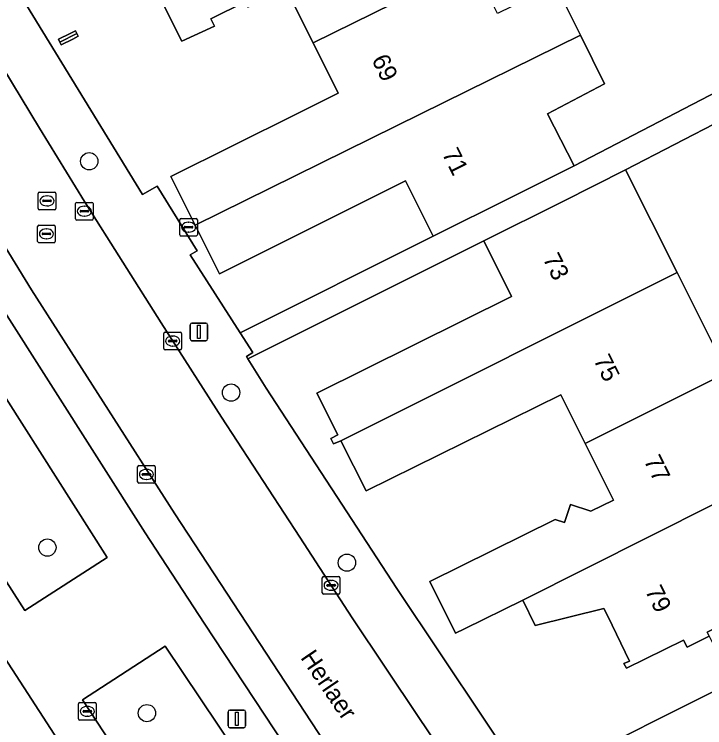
# Model space of a CAD drawing. Extents: x 157793 to 159380, y 380877 to 382313.
# Drawn here: x 158180.74 to 158219.83, y 381465.24 to 381505.64 of the extents above; entities that cross this region are included whole.
import ezdxf

# ---------------------------------------------------------------- set-up
doc = ezdxf.new("R2010")
doc.units = 0
for name, color, linetype in [('IMGEO_Boom', 7, 'Continuous'), ('IMGEO_Erf', 7, 'Continuous'), ('IMGEO_Groenvoorziening', 7, 'Continuous'), ('IMGEO_Kolk', 7, 'Continuous'), ('IMGEO_Lichtmast', 7, 'Continuous'), ('IMGEO_Openbare_ruimte_label', 7, 'Continuous'), ('IMGEO_Pand', 7, 'Continuous'), ('IMGEO_Pand_nummerreeks', 7, 'Continuous'), ('IMGEO_Parkeervlak_open', 7, 'Continuous'), ('IMGEO_Rijbaan_lokaal_open', 7, 'Continuous'), ('IMGEO_Rioolput', 7, 'Continuous'), ('IMGEO_Voetpad_open', 7, 'Continuous')]:
    doc.layers.add(name, color=color, linetype=linetype)

msp = doc.modelspace()

# ---------------------------------------------------------------- linework, layer by layer
at = {"layer": 'IMGEO_Boom'}
for centre in [(158184.986, 381497.315), (158193.018, 381484.217), (158182.617, 381475.445), (158199.576, 381474.588), (158188.251, 381466.07)]:
    msp.add_circle(centre, 0.489, dxfattribs=at)
at = {"layer": 'IMGEO_Erf'}
for points in [[(158181.083, 381506.764), (158188.007, 381495.43), (158188.833, 381495.915), (158191.096, 381492.237), (158190.7, 381492.013), (158193.532, 381487.602), (158204.46, 381493.068), (158202.889, 381496.209), (158192.361, 381490.942), (158190.983, 381493.696), (158189.601, 381496.459), (158196.733, 381500), (158199.076, 381501.163), (158197.657, 381504.028), (158196.125, 381507.123)], [(158211.379, 381507.303), (158212.789, 381504.457), (158214.158, 381501.692), (158210.927, 381500), (158212.434, 381497.057), (158222.963, 381502.539)], [(158193.811, 381506.345), (158191.865, 381505.385), (158192.073, 381504.963), (158190.226, 381504.118), (158188.912, 381506.75)], [(158223.667, 381501.139), (158215.352, 381496.827), (158218.262, 381491.01), (158221.092, 381485.355)], [(158196.197, 381444.89), (158187.383, 381458.121), (158179.308, 381470.565), (158168.261, 381487.773), (158162.146, 381497.834)], [(158207.322, 381492.809), (158193.967, 381486.126), (158195.005, 381484.47), (158202.402, 381473.13), (158209.819, 381462.024), (158210.491, 381462.328), (158213.909, 381457.425), (158213.23, 381457.086), (158215.155, 381454.363), (158215.033, 381454.286), (158220.925, 381445.928)], [(158220.077, 381470.42), (158218.834, 381469.798), (158218.628, 381470.209), (158215.399, 381468.609), (158215.254, 381468.886), (158215.575, 381469.021), (158214.338, 381471.558), (158214.128, 381471.988), (158210.227, 381471.034), (158209.526, 381472.475), (158206.23, 381470.85), (158205.719, 381470.594), (158204.278, 381473.518), (158211.36, 381477.029), (158211.892, 381476.869), (158212.238, 381477.889), (158213.378, 381477.503), (158214.666, 381478.129), (158213.061, 381481.336), (158211.687, 381484.083), (158200.657, 381478.649), (158199.236, 381481.489), (158198.823, 381481.322), (158198.673, 381481.621), (158199.069, 381481.82), (158197.881, 381484.193), (158208.896, 381489.662), (158207.322, 381492.809)], [(158224.056, 381462.381), (158214.071, 381457.386), (158212.773, 381459.981), (158211.362, 381462.801), (158221.381, 381467.814)]]:
    msp.add_lwpolyline(points, dxfattribs=at)
msp.add_lwpolyline([(158184.213, 381504.7), (158184.291, 381504.541), (158184.365, 381504.392), (158184.052, 381504.237), (158183.399, 381503.914), (158183.324, 381504.066), (158183.247, 381504.221), (158183.899, 381504.544)], close=True, dxfattribs=at)
at = {"layer": 'IMGEO_Groenvoorziening'}
for points in [[(158177.476, 381488.273), (158172.552, 381485.604), (158181.337, 381471.872), (158186.001, 381474.885)], [(158189.292, 381469.869), (158184.614, 381466.823), (158191.129, 381456.883), (158198.958, 381445.276), (158200.372, 381442.689), (158206.681, 381444.18), (158201.324, 381451.912)]]:
    msp.add_lwpolyline(points, close=True, dxfattribs=at)
at = {"layer": 'IMGEO_Kolk'}
for p, q in [((158190.108, 381493.156), (158190.108, 381494.008)), ((158190.183, 381494.082), (158191.035, 381494.082)), ((158191.109, 381494.008), (158191.109, 381493.156)), ((158190.367, 381493.576), (158190.367, 381493.588)), ((158190.41, 381493.625), (158190.808, 381493.625)), ((158190.596, 381493.862), (158190.621, 381493.862)), ((158190.851, 381493.588), (158190.851, 381493.576)), ((158190.805, 381493.539), (158190.407, 381493.539)), ((158190.619, 381493.302), (158190.594, 381493.302)), ((158191.035, 381493.082), (158190.183, 381493.082)), ((158189.211, 381486.71), (158189.211, 381487.562)), ((158189.286, 381487.636), (158190.138, 381487.636)), ((158190.212, 381487.562), (158190.212, 381486.71)), ((158189.47, 381487.13), (158189.47, 381487.142)), ((158189.513, 381487.179), (158189.911, 381487.179)), ((158189.699, 381487.416), (158189.724, 381487.416)), ((158189.954, 381487.142), (158189.954, 381487.13)), ((158189.908, 381487.093), (158189.51, 381487.093)), ((158189.722, 381486.856), (158189.697, 381486.856)), ((158190.138, 381486.636), (158189.286, 381486.636)), ((158187.725, 381479.16), (158187.725, 381480.012)), ((158187.8, 381480.086), (158188.652, 381480.086)), ((158188.213, 381479.866), (158188.238, 381479.866)), ((158188.726, 381480.012), (158188.726, 381479.16)), ((158187.984, 381479.58), (158187.984, 381479.592)), ((158188.422, 381479.543), (158188.024, 381479.543)), ((158188.027, 381479.629), (158188.425, 381479.629)), ((158188.468, 381479.592), (158188.468, 381479.58)), ((158188.652, 381479.086), (158187.8, 381479.086)), ((158188.236, 381479.306), (158188.211, 381479.306)), ((158198.256, 381473.808), (158199.108, 381473.808)), ((158198.181, 381472.882), (158198.181, 381473.734)), ((158198.669, 381473.588), (158198.694, 381473.588)), ((158199.182, 381473.734), (158199.182, 381472.882)), ((158198.44, 381473.302), (158198.44, 381473.314)), ((158198.878, 381473.265), (158198.48, 381473.265)), ((158198.483, 381473.351), (158198.881, 381473.351)), ((158198.692, 381473.028), (158198.667, 381473.028)), ((158198.924, 381473.314), (158198.924, 381473.302)), ((158199.108, 381472.808), (158198.256, 381472.808)), ((158184.377, 381465.747), (158184.377, 381466.599)), ((158184.452, 381466.673), (158185.304, 381466.673)), ((158185.378, 381466.599), (158185.378, 381465.747)), ((158184.636, 381466.167), (158184.636, 381466.179)), ((158185.074, 381466.13), (158184.676, 381466.13)), ((158184.679, 381466.216), (158185.077, 381466.216)), ((158184.865, 381466.453), (158184.89, 381466.453)), ((158185.12, 381466.179), (158185.12, 381466.167)), ((158184.888, 381465.893), (158184.863, 381465.893)), ((158185.304, 381465.673), (158184.452, 381465.673))]:
    msp.add_line(p, q, dxfattribs=at)
for points in [[(158190.108, 381493.156), (158190.108, 381494.008)], [(158190.183, 381494.082), (158191.035, 381494.082)], [(158191.109, 381494.008), (158191.109, 381493.156)], [(158191.035, 381493.082), (158190.183, 381493.082)], [(158189.211, 381486.71), (158189.211, 381487.562)], [(158189.286, 381487.636), (158190.138, 381487.636)], [(158190.212, 381487.562), (158190.212, 381486.71)], [(158190.138, 381486.636), (158189.286, 381486.636)], [(158187.725, 381479.16), (158187.725, 381480.012)], [(158187.8, 381480.086), (158188.652, 381480.086)], [(158188.726, 381480.012), (158188.726, 381479.16)], [(158188.652, 381479.086), (158187.8, 381479.086)], [(158198.256, 381473.808), (158199.108, 381473.808)], [(158198.181, 381472.882), (158198.181, 381473.734)], [(158199.182, 381473.734), (158199.182, 381472.882)], [(158199.108, 381472.808), (158198.256, 381472.808)], [(158184.377, 381465.747), (158184.377, 381466.599)], [(158184.452, 381466.673), (158185.304, 381466.673)], [(158185.378, 381466.599), (158185.378, 381465.747)], [(158185.304, 381465.673), (158184.452, 381465.673)]]:
    msp.add_lwpolyline(points, dxfattribs=at)
for centre, radius, start, end in [((158190.185, 381494.006), 0.0765, 91.552, 178.448), ((158190.185, 381494.006), 0.0765, 91.552, 178.448), ((158191.033, 381494.006), 0.0765, 1.552, 88.448), ((158191.033, 381494.006), 0.0765, 1.552, 88.448), ((158190.407, 381493.585), 0.0403, 85.8775, 175.7526), ((158190.404, 381493.575), 0.0366, 178.938, 274.7102), ((158190.808, 381493.582), 0.043, 264.8664, 352.4533), ((158190.812, 381493.587), 0.0386, 1.7309, 96.639), ((158190.185, 381493.158), 0.0765, 181.552, 268.448), ((158190.185, 381493.158), 0.0765, 181.552, 268.448), ((158191.033, 381493.158), 0.0765, 271.552, 358.448), ((158191.033, 381493.158), 0.0765, 271.552, 358.448), ((158189.288, 381487.56), 0.0765, 91.552, 178.448), ((158189.288, 381487.56), 0.0765, 91.552, 178.448), ((158190.136, 381487.56), 0.0765, 1.552, 88.448), ((158190.136, 381487.56), 0.0765, 1.552, 88.448), ((158189.51, 381487.139), 0.0403, 85.8775, 175.7526), ((158189.507, 381487.129), 0.0366, 178.938, 274.7102), ((158189.911, 381487.136), 0.043, 264.8664, 352.4533), ((158189.915, 381487.141), 0.0386, 1.7309, 96.639), ((158189.288, 381486.712), 0.0765, 181.552, 268.448), ((158189.288, 381486.712), 0.0765, 181.552, 268.448), ((158190.136, 381486.712), 0.0765, 271.552, 358.448), ((158190.136, 381486.712), 0.0765, 271.552, 358.448), ((158187.802, 381480.01), 0.0765, 91.552, 178.448), ((158187.802, 381480.01), 0.0765, 91.552, 178.448), ((158188.65, 381480.01), 0.0765, 1.552, 88.448), ((158188.65, 381480.01), 0.0765, 1.552, 88.448), ((158188.024, 381479.589), 0.0403, 85.8775, 175.7526), ((158188.021, 381479.579), 0.0366, 178.938, 274.7102), ((158188.425, 381479.586), 0.043, 264.8664, 352.4533), ((158188.429, 381479.591), 0.0386, 1.7309, 96.639), ((158187.802, 381479.162), 0.0765, 181.552, 268.448), ((158187.802, 381479.162), 0.0765, 181.552, 268.448), ((158188.65, 381479.162), 0.0765, 271.552, 358.448), ((158188.65, 381479.162), 0.0765, 271.552, 358.448), ((158198.258, 381473.732), 0.0765, 91.552, 178.448), ((158198.258, 381473.732), 0.0765, 91.552, 178.448), ((158199.106, 381473.732), 0.0765, 1.552, 88.448), ((158199.106, 381473.732), 0.0765, 1.552, 88.448), ((158198.48, 381473.311), 0.0403, 85.8775, 175.7526), ((158198.477, 381473.301), 0.0366, 178.938, 274.7102), ((158198.881, 381473.308), 0.043, 264.8664, 352.4533), ((158198.885, 381473.313), 0.0386, 1.7309, 96.639), ((158198.258, 381472.884), 0.0765, 181.552, 268.448), ((158198.258, 381472.884), 0.0765, 181.552, 268.448), ((158199.106, 381472.884), 0.0765, 271.552, 358.448), ((158199.106, 381472.884), 0.0765, 271.552, 358.448), ((158184.454, 381466.597), 0.0765, 91.552, 178.448), ((158184.454, 381466.597), 0.0765, 91.552, 178.448), ((158185.302, 381466.597), 0.0765, 1.552, 88.448), ((158185.302, 381466.597), 0.0765, 1.552, 88.448), ((158184.676, 381466.176), 0.0403, 85.8775, 175.7526), ((158184.673, 381466.166), 0.0366, 178.938, 274.7102), ((158185.077, 381466.173), 0.043, 264.8664, 352.4533), ((158185.081, 381466.178), 0.0386, 1.7309, 96.639), ((158184.454, 381465.749), 0.0765, 181.552, 268.448), ((158184.454, 381465.749), 0.0765, 181.552, 268.448), ((158185.302, 381465.749), 0.0765, 271.552, 358.448), ((158185.302, 381465.749), 0.0765, 271.552, 358.448)]:
    msp.add_arc(centre, radius, start, end, dxfattribs=at)
for centre, major_axis, ratio, start_param, end_param in [((158190.595, 381493.582), (-0.387, 0.002), 0.722429, 4.712389, 7.853982), ((158190.62, 381493.582), (-0.39, 0.002), 0.717154, 1.570796, 4.712389), ((158189.698, 381487.136), (-0.387, 0.002), 0.722429, 4.712389, 7.853982), ((158189.723, 381487.136), (-0.39, 0.002), 0.717154, 1.570796, 4.712389), ((158188.212, 381479.586), (-0.387, 0.002), 0.722429, 4.712389, 7.853982), ((158188.237, 381479.586), (-0.39, 0.002), 0.717154, 1.570796, 4.712389), ((158198.668, 381473.308), (-0.387, 0.002), 0.722429, 4.712389, 7.853982), ((158198.693, 381473.308), (-0.39, 0.002), 0.717154, 1.570796, 4.712389), ((158184.864, 381466.173), (-0.387, 0.002), 0.722429, 4.712389, 7.853982), ((158184.889, 381466.173), (-0.39, 0.002), 0.717154, 1.570796, 4.712389)]:
    msp.add_ellipse(centre, major_axis=major_axis, ratio=ratio, start_param=start_param, end_param=end_param, dxfattribs=at)
at = {"layer": 'IMGEO_Lichtmast'}
for p, q in [((158190.701, 381487.254), (158190.701, 381488.054)), ((158190.701, 381488.054), (158190.701, 381487.254)), ((158190.801, 381488.154), (158191.591, 381488.154)), ((158191.591, 381488.154), (158190.801, 381488.154)), ((158191.691, 381488.054), (158191.691, 381487.254)), ((158191.691, 381487.254), (158191.691, 381488.054)), ((158191.591, 381487.154), (158190.801, 381487.154)), ((158190.801, 381487.154), (158191.591, 381487.154)), ((158192.851, 381465.343), (158192.851, 381466.143)), ((158192.851, 381466.143), (158192.851, 381465.343)), ((158192.951, 381466.243), (158193.741, 381466.243)), ((158193.741, 381466.243), (158192.951, 381466.243)), ((158193.841, 381466.143), (158193.841, 381465.343)), ((158193.841, 381465.343), (158193.841, 381466.143)), ((158193.741, 381465.243), (158192.951, 381465.243)), ((158192.951, 381465.243), (158193.741, 381465.243))]:
    msp.add_line(p, q, dxfattribs=at)
for points in [[(158191.121, 381488.029), (158191.271, 381488.029), (158191.271, 381487.279), (158191.121, 381487.279), (158191.121, 381488.029)], [(158193.271, 381466.118), (158193.421, 381466.118), (158193.421, 381465.368), (158193.271, 381465.368), (158193.271, 381466.118)]]:
    msp.add_lwpolyline(points, dxfattribs=at)
for centre, start, end in [((158190.801, 381488.054), 90, 180), ((158190.801, 381488.054), 90, 180), ((158191.591, 381488.054), 0, 90), ((158191.591, 381488.054), 360, 90), ((158190.801, 381487.254), 180, 270), ((158190.801, 381487.254), 180, 270), ((158191.591, 381487.254), 270, 0), ((158191.591, 381487.254), 270, 0), ((158192.951, 381466.143), 90, 180), ((158192.951, 381466.143), 90, 180), ((158193.741, 381466.143), 0, 90), ((158193.741, 381466.143), 360, 90), ((158192.951, 381465.343), 180, 270), ((158192.951, 381465.343), 180, 270), ((158193.741, 381465.343), 270, 0), ((158193.741, 381465.343), 270, 0)]:
    msp.add_arc(centre, 0.1, start, end, dxfattribs=at)
at = {"layer": 'IMGEO_Pand'}
for points in [[(158205.616, 381507.956), (158205.476, 381508.238), (158205.222, 381508.751), (158204.106, 381511.004), (158206.692, 381512.285), (158205.402, 381514.888), (158188.912, 381506.75), (158190.226, 381504.118), (158192.073, 381504.963), (158191.865, 381505.385), (158193.811, 381506.345), (158193.957, 381506.049), (158196.125, 381507.123), (158197.657, 381504.028)], [(158212.789, 381504.457), (158211.379, 381507.303), (158208.099, 381505.678), (158206.609, 381508.687), (158205.578, 381508.178), (158205.673, 381507.984), (158205.616, 381507.956), (158197.657, 381504.028), (158199.076, 381501.163), (158196.733, 381500), (158189.601, 381496.459), (158190.983, 381493.696), (158203.757, 381500)], [(158183.324, 381504.066), (158184.291, 381504.541), (158184.213, 381504.7), (158183.899, 381504.544), (158183.247, 381504.221)], [(158184.052, 381504.237), (158184.365, 381504.392), (158184.291, 381504.541), (158183.324, 381504.066), (158183.399, 381503.914)], [(158212.789, 381504.457), (158203.757, 381500), (158190.983, 381493.696), (158192.361, 381490.942), (158202.889, 381496.209), (158204.46, 381493.068), (158208.932, 381495.305), (158212.434, 381497.057), (158210.927, 381500), (158214.158, 381501.692)], [(158199.236, 381481.489), (158218.262, 381491.01), (158215.352, 381496.827), (158211.794, 381495.047), (158207.322, 381492.809), (158208.896, 381489.662), (158197.881, 381484.193), (158199.069, 381481.82), (158198.673, 381481.621), (158198.823, 381481.322)], [(158221.092, 381485.355), (158218.262, 381491.01), (158199.236, 381481.489), (158200.657, 381478.649), (158211.687, 381484.083), (158213.061, 381481.336)], [(158221.092, 381485.355), (158213.061, 381481.336), (158214.666, 381478.129), (158213.378, 381477.503), (158212.238, 381477.889), (158211.892, 381476.869), (158211.36, 381477.029), (158204.278, 381473.518), (158205.719, 381470.594), (158206.23, 381470.85), (158209.526, 381472.475), (158223.921, 381479.701)], [(158209.526, 381472.475), (158210.227, 381471.034), (158214.128, 381471.988), (158214.338, 381471.558), (158215.575, 381469.021), (158215.254, 381468.886), (158215.399, 381468.609), (158218.628, 381470.209), (158218.834, 381469.798), (158220.077, 381470.42), (158219.962, 381470.65), (158226.59, 381473.967), (158226.441, 381474.264), (158226.601, 381474.344), (158225.241, 381477.063), (158225.983, 381477.435), (158227.662, 381478.929), (158226.602, 381481.047), (158223.921, 381479.701)], [(158212.773, 381459.981), (158230.582, 381468.893), (158227.604, 381474.845), (158226.869, 381474.478), (158226.601, 381474.344), (158226.441, 381474.264), (158226.59, 381473.967), (158219.962, 381470.65), (158220.077, 381470.42), (158221.381, 381467.814), (158211.362, 381462.801)]]:
    msp.add_lwpolyline(points, close=True, dxfattribs=at)
at = {"layer": 'IMGEO_Parkeervlak_open'}
for points in [[(158211.021, 381445.909), (158206.462, 381452.438), (158198.314, 381464.433), (158189.837, 381477.355), (158181.714, 381490.043), (158173.283, 381503.774), (158168.753, 381511.382), (158162.831, 381521.68), (158157.089, 381532.018), (158155.415, 381535.054), (158148.825, 381547.056)], [(158148.449, 381543.56), (158152.339, 381536.528), (158154.693, 381532.233), (158161.1, 381520.669), (158163.584, 381516.344), (158167.051, 381510.356), (158171.612, 381502.714), (158176.956, 381493.981), (158180.068, 381488.973), (158188.156, 381476.274), (158191.493, 381471.166), (158196.6, 381463.411), (158207.708, 381447.175)]]:
    msp.add_lwpolyline(points, dxfattribs=at)
at = {"layer": 'IMGEO_Rijbaan_lokaal_open'}
msp.add_lwpolyline([(158168.753, 381511.382), (158173.283, 381503.774), (158181.714, 381490.043), (158189.837, 381477.355), (158198.314, 381464.433), (158206.462, 381452.438), (158211.021, 381445.909), (158211.178, 381445.694), (158214.031, 381441.646), (158215.433, 381439.703), (158215.544, 381439.782), (158219.673, 381442.728), (158211.139, 381454.855), (158207.189, 381460.583), (158203.651, 381465.824), (158199.88, 381471.47), (158196.908, 381476.029), (158192.482, 381482.833), (158189.052, 381488.161), (158184.727, 381495.042), (158182.168, 381499.189), (158178.499, 381505.249), (158175.691, 381509.903)], dxfattribs=at)
at = {"layer": 'IMGEO_Rioolput'}
for p, q in [((158182.096, 381494.646), (158182.096, 381495.498)), ((158182.171, 381495.572), (158183.023, 381495.572)), ((158182.584, 381495.352), (158182.609, 381495.352)), ((158183.097, 381495.498), (158183.097, 381494.646)), ((158182.355, 381495.066), (158182.355, 381495.078)), ((158182.793, 381495.029), (158182.395, 381495.029)), ((158182.398, 381495.115), (158182.796, 381495.115)), ((158182.607, 381494.792), (158182.582, 381494.792)), ((158182.839, 381495.078), (158182.839, 381495.066)), ((158184.211, 381494.064), (158184.211, 381494.916)), ((158184.286, 381494.99), (158185.138, 381494.99)), ((158185.212, 381494.916), (158185.212, 381494.064)), ((158183.023, 381494.572), (158182.171, 381494.572)), ((158184.47, 381494.484), (158184.47, 381494.496)), ((158184.908, 381494.447), (158184.51, 381494.447)), ((158184.513, 381494.533), (158184.911, 381494.533)), ((158184.699, 381494.77), (158184.724, 381494.77)), ((158184.954, 381494.496), (158184.954, 381494.484)), ((158185.138, 381493.99), (158184.286, 381493.99)), ((158184.722, 381494.21), (158184.697, 381494.21)), ((158182.064, 381492.78), (158182.064, 381493.632)), ((158182.139, 381493.706), (158182.991, 381493.706)), ((158183.065, 381493.632), (158183.065, 381492.78)), ((158182.323, 381493.2), (158182.323, 381493.212)), ((158182.366, 381493.249), (158182.764, 381493.249)), ((158182.552, 381493.486), (158182.577, 381493.486)), ((158182.807, 381493.212), (158182.807, 381493.2)), ((158182.761, 381493.163), (158182.363, 381493.163)), ((158182.575, 381492.926), (158182.55, 381492.926)), ((158182.991, 381492.706), (158182.139, 381492.706))]:
    msp.add_line(p, q, dxfattribs=at)
for points in [[(158182.096, 381494.646), (158182.096, 381495.498)], [(158182.171, 381495.572), (158183.023, 381495.572)], [(158183.097, 381495.498), (158183.097, 381494.646)], [(158184.211, 381494.064), (158184.211, 381494.916)], [(158184.286, 381494.99), (158185.138, 381494.99)], [(158185.212, 381494.916), (158185.212, 381494.064)], [(158183.023, 381494.572), (158182.171, 381494.572)], [(158185.138, 381493.99), (158184.286, 381493.99)], [(158182.064, 381492.78), (158182.064, 381493.632)], [(158182.139, 381493.706), (158182.991, 381493.706)], [(158183.065, 381493.632), (158183.065, 381492.78)], [(158182.991, 381492.706), (158182.139, 381492.706)]]:
    msp.add_lwpolyline(points, dxfattribs=at)
for centre, radius, start, end in [((158182.173, 381495.496), 0.0765, 91.552, 178.448), ((158182.173, 381495.496), 0.0765, 91.552, 178.448), ((158183.021, 381495.496), 0.0765, 1.552, 88.448), ((158183.021, 381495.496), 0.0765, 1.552, 88.448), ((158182.395, 381495.075), 0.0403, 85.8775, 175.7526), ((158182.392, 381495.065), 0.0366, 178.938, 274.7102), ((158182.796, 381495.072), 0.043, 264.8664, 352.4533), ((158182.8, 381495.077), 0.0386, 1.7309, 96.639), ((158184.288, 381494.914), 0.0765, 91.552, 178.448), ((158184.288, 381494.914), 0.0765, 91.552, 178.448), ((158185.136, 381494.914), 0.0765, 1.552, 88.448), ((158185.136, 381494.914), 0.0765, 1.552, 88.448), ((158182.173, 381494.648), 0.0765, 181.552, 268.448), ((158182.173, 381494.648), 0.0765, 181.552, 268.448), ((158183.021, 381494.648), 0.0765, 271.552, 358.448), ((158183.021, 381494.648), 0.0765, 271.552, 358.448), ((158184.51, 381494.493), 0.0403, 85.8775, 175.7526), ((158184.507, 381494.483), 0.0366, 178.938, 274.7102), ((158184.911, 381494.49), 0.043, 264.8664, 352.4533), ((158184.915, 381494.495), 0.0386, 1.7309, 96.639), ((158184.288, 381494.066), 0.0765, 181.552, 268.448), ((158184.288, 381494.066), 0.0765, 181.552, 268.448), ((158185.136, 381494.066), 0.0765, 271.552, 358.448), ((158185.136, 381494.066), 0.0765, 271.552, 358.448), ((158182.141, 381493.63), 0.0765, 91.552, 178.448), ((158182.141, 381493.63), 0.0765, 91.552, 178.448), ((158182.989, 381493.63), 0.0765, 1.552, 88.448), ((158182.989, 381493.63), 0.0765, 1.552, 88.448), ((158182.363, 381493.209), 0.0403, 85.8775, 175.7526), ((158182.36, 381493.199), 0.0366, 178.938, 274.7102), ((158182.764, 381493.206), 0.043, 264.8664, 352.4533), ((158182.768, 381493.211), 0.0386, 1.7309, 96.639), ((158182.141, 381492.782), 0.0765, 181.552, 268.448), ((158182.141, 381492.782), 0.0765, 181.552, 268.448), ((158182.989, 381492.782), 0.0765, 271.552, 358.448), ((158182.989, 381492.782), 0.0765, 271.552, 358.448)]:
    msp.add_arc(centre, radius, start, end, dxfattribs=at)
for centre, major_axis, ratio, start_param, end_param in [((158182.583, 381495.072), (-0.387, 0.002), 0.722429, 4.712389, 7.853982), ((158182.608, 381495.072), (-0.39, 0.002), 0.717154, 1.570796, 4.712389), ((158184.698, 381494.49), (-0.387, 0.002), 0.722429, 4.712389, 7.853982), ((158184.723, 381494.49), (-0.39, 0.002), 0.717154, 1.570796, 4.712389), ((158182.551, 381493.206), (-0.387, 0.002), 0.722429, 4.712389, 7.853982), ((158182.576, 381493.206), (-0.39, 0.002), 0.717154, 1.570796, 4.712389)]:
    msp.add_ellipse(centre, major_axis=major_axis, ratio=ratio, start_param=start_param, end_param=end_param, dxfattribs=at)
at = {"layer": 'IMGEO_Voetpad_open'}
for points in [[(158153.644, 381549.128), (158159.97, 381537.562), (158161.594, 381534.598), (158163.996, 381530.272), (158165.872, 381526.867), (158169.218, 381520.936), (158171.659, 381516.762), (158175.691, 381509.903), (158178.499, 381505.249), (158182.168, 381499.189), (158184.727, 381495.042), (158189.052, 381488.161), (158192.482, 381482.833), (158196.908, 381476.029), (158199.88, 381471.47), (158203.651, 381465.824), (158207.189, 381460.583), (158211.139, 381454.855), (158219.673, 381442.728), (158220.405, 381441.765), (158225.147, 381444.74)], [(158188.156, 381476.274), (158180.068, 381488.973), (158176.956, 381493.981), (158171.612, 381502.714), (158167.051, 381510.356), (158163.584, 381516.344), (158161.1, 381520.669), (158154.693, 381532.233), (158152.339, 381536.528), (158148.449, 381543.56)], [(158220.925, 381445.928), (158215.033, 381454.286), (158215.155, 381454.363), (158213.23, 381457.086), (158213.909, 381457.425), (158210.491, 381462.328), (158209.819, 381462.024), (158202.402, 381473.13), (158195.005, 381484.47), (158193.967, 381486.126), (158193.881, 381486.263), (158194.249, 381486.486), (158193.532, 381487.602), (158190.7, 381492.013), (158191.096, 381492.237), (158188.833, 381495.915), (158188.007, 381495.43), (158181.083, 381506.764)], [(158222.963, 381502.539), (158212.434, 381497.057), (158208.932, 381495.305), (158204.46, 381493.068), (158193.532, 381487.602), (158194.249, 381486.486), (158193.881, 381486.263), (158193.967, 381486.126), (158207.322, 381492.809), (158211.794, 381495.047), (158215.352, 381496.827), (158223.667, 381501.139)], [(158162.146, 381497.834), (158168.261, 381487.773), (158179.308, 381470.565), (158187.383, 381458.121), (158196.197, 381444.89)], [(158207.708, 381447.175), (158196.6, 381463.411), (158191.493, 381471.166), (158188.156, 381476.274)]]:
    msp.add_lwpolyline(points, dxfattribs=at)
for points in [[(158181.337, 381471.872), (158172.552, 381485.604), (158177.476, 381488.273), (158186.001, 381474.885)], [(158189.292, 381469.869), (158201.324, 381451.912), (158206.681, 381444.18), (158200.372, 381442.689), (158198.958, 381445.276), (158191.129, 381456.883), (158184.614, 381466.823)]]:
    msp.add_lwpolyline(points, close=True, dxfattribs=at)

# ---------------------------------------------------------------- texts
at = {"layer": 'IMGEO_Openbare_ruimte_label'}
msp.add_text('Herlaer', height=1, rotation=304.1191, dxfattribs=at).set_placement((158196.915, 381469.215))
at = {"layer": 'IMGEO_Pand_nummerreeks'}
for s, rotation, p in [('69', 296.2642, (158200.95, 381503.068)), ('71', 296.5723, (158204.935, 381497.752)), ('73', 296.5767, (158210.641, 381491.807)), ('75', 296.5767, (158213.511, 381486.071)), ('77', 296.5804, (158216.363, 381480.371)), ('79', 295.9984, (158216.44, 381473))]:
    msp.add_text(s, height=1, rotation=rotation, dxfattribs=at).set_placement(p)

doc.saveas('drawing.dxf')
